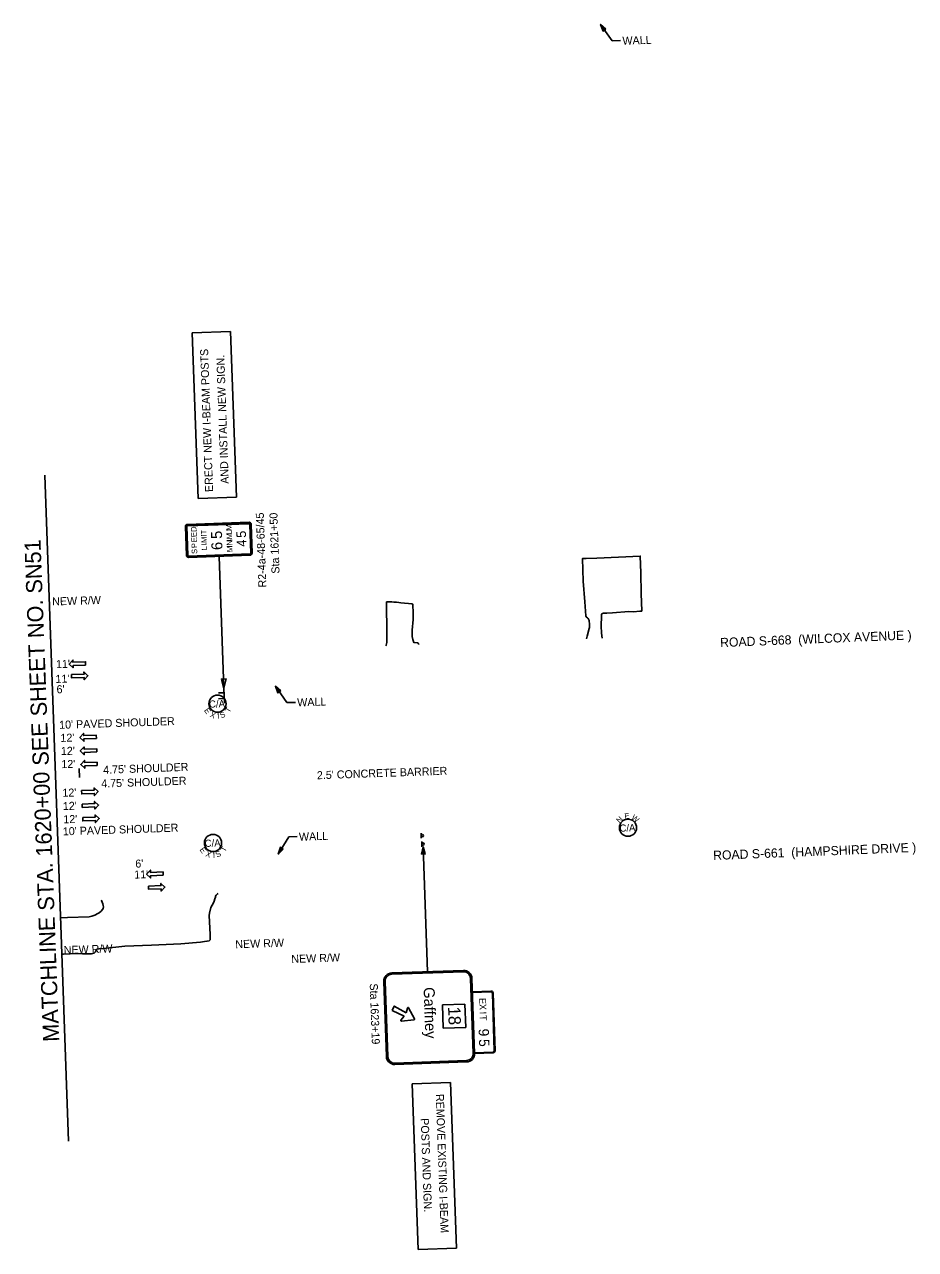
# Model space of a CAD drawing. Extents: x 1808944 to 1810496, y 1189647 to 1190718.
# Drawn here: x 1808944 to 1809723, y 1189647 to 1190718 of the extents above; entities that cross this region are included whole.
import ezdxf

# ---------------------------------------------------------------- set-up
doc = ezdxf.new("R2010")
doc.units = 0
for name, color, linetype in [('RD_EX_Road', 7, 'Continuous'), ('RD_HC_Data_Tic', 7, 'Continuous'), ('RD_PD_Final_LnLine', 7, 'Continuous'), ('RD_PD_Final_TX', 7, 'Continuous'), ('RD_PD_RW_TX', 7, 'Continuous'), ('RD_SHT_MatchLine', 7, 'Continuous'), ('RD_SHT_TX', 7, 'Continuous'), ('RD_Sketch10', 7, 'Continuous'), ('RD_Sketch8', 7, 'Continuous'), ('RD_TX_RoadID', 7, 'Continuous'), ('SN_P_Signs', 7, 'Continuous'), ('TERMINATOR', 7, 'Continuous')]:
    doc.layers.add(name, color=color, linetype=linetype)

# ---------------------------------------------------------------- blocks, each defined once
blk = doc.blocks.new('SARRW2')
at = {"layer": 'RD_PD_Final_LnLine'}
blk.add_lwpolyline([(-12, 1.2), (-12, -1.2), (-2.83, -1.2), (-2.83, -2.83), (0, 0), (-2.83, 2.83), (-2.83, 1.2)], close=True, dxfattribs=at)

msp = doc.modelspace()

# ---------------------------------------------------------------- linework, layer by layer
at = {"layer": 'RD_EX_Road'}
for points in [[(1809449, 1190181.4), (1809448.6, 1190183.4), (1809448.4, 1190186.1), (1809448.2, 1190191.8), (1809448.3, 1190200.9), (1809448.3, 1190201.5), (1809448.5, 1190202.1), (1809448.7, 1190202.6), (1809449.2, 1190202.9), (1809450.1, 1190203.1), (1809451.3, 1190203.3), (1809453.1, 1190203.3), (1809457.9, 1190203.6), (1809472.4, 1190204.6), (1809476.4, 1190204.5), (1809481.9, 1190204.9), (1809483.6, 1190205), (1809483.2, 1190220.5), (1809482.9, 1190238.4), (1809482.3, 1190253.2), (1809444.4, 1190251.3), (1809435, 1190251), (1809431.6, 1190250.9), (1809432.4, 1190231.2), (1809433.7, 1190213.1), (1809434.6, 1190200.8), (1809434.8, 1190200.1), (1809435.2, 1190199.7), (1809436, 1190199), (1809436.6, 1190198.5), (1809437, 1190198), (1809437.3, 1190197.4), (1809437.5, 1190196.7), (1809437.6, 1190195.7), (1809437.8, 1190194.5), (1809437.9, 1190193.5), (1809437.9, 1190192.4), (1809437.9, 1190191.6), (1809437.8, 1190190.8), (1809437.6, 1190189.7), (1809435.9, 1190183), (1809435.3, 1190180.9)], [(1809288.8, 1190175.7), (1809288.3, 1190176.4), (1809287.6, 1190177.3), (1809284.1, 1190177.7), (1809283.3, 1190180.2), (1809282.8, 1190182.8), (1809282.7, 1190184.2), (1809282.7, 1190188.3), (1809283.5, 1190197.6), (1809283.5, 1190204.7), (1809283.4, 1190209.3), (1809283.2, 1190211), (1809282.3, 1190211.5), (1809279.4, 1190211.7), (1809275.9, 1190212), (1809272.9, 1190212.3), (1809271.1, 1190212.5), (1809269, 1190212.7), (1809266.6, 1190212.9), (1809264.8, 1190213), (1809263, 1190213.1), (1809261.4, 1190213.1), (1809260.3, 1190213), (1809260.3, 1190207.1), (1809260.7, 1190190.9), (1809260.7, 1190180.5), (1809260.6, 1190177.5), (1809260.1, 1190175.3), (1809259.8, 1190174.7)], [(1808976.2, 1189904.9), (1808977.7, 1189905), (1808989.7, 1189905.4), (1808994.4, 1189905.3), (1808996.7, 1189905.3), (1808999.9, 1189905.2), (1809002.2, 1189905.3), (1809004.5, 1189905.7), (1809005.6, 1189907), (1809006.4, 1189908.5), (1809007, 1189909.2), (1809008.8, 1189909.6), (1809012.6, 1189910), (1809031.3, 1189911.8), (1809054.7, 1189912.8), (1809080.3, 1189914), (1809097.5, 1189915.5), (1809101, 1189915.9), (1809103.2, 1189916.2), (1809105.2, 1189916.6), (1809106.1, 1189917.5), (1809106.1, 1189919.9), (1809105.9, 1189922), (1809105.2, 1189938.6), (1809105.4, 1189940.9), (1809106.7, 1189945.8), (1809107.7, 1189947.8), (1809108.8, 1189949.7), (1809109.5, 1189951.4), (1809110.2, 1189953.3), (1809110.6, 1189954.9), (1809110.8, 1189955.7), (1809111.2, 1189956.5), (1809111.8, 1189957.1), (1809112.5, 1189957.7), (1809113, 1189957.9)], [(1809010.6, 1189952.2), (1809010.8, 1189951.8), (1809011.4, 1189950.3), (1809012, 1189948.9), (1809012.5, 1189947.6), (1809012.6, 1189946.3), (1809012.3, 1189945), (1809011.8, 1189944), (1809010.7, 1189942.6), (1809009, 1189941.2), (1809007.7, 1189940.5), (1809005, 1189938.9), (1809002.5, 1189938.1), (1809000.1, 1189937.6), (1808981.2, 1189936.9), (1808975.1, 1189936.7)]]:
    msp.add_lwpolyline(points, dxfattribs=at)
at = {"layer": 'RD_HC_Data_Tic'}
msp.add_line((1808991.6, 1190059.4), (1808991.3, 1190067.4), dxfattribs=at)
at = {"layer": 'RD_PD_Final_TX'}
for p, q in [((1809447.5, 1190718.2), (1809457.6, 1190703.8)), ((1809465.1, 1190704.1), (1809457.6, 1190703.8)), ((1809163.1, 1190139.3), (1809173.2, 1190125)), ((1809180.6, 1190125.2), (1809173.2, 1190125)), ((1809174.7, 1190007.5), (1809165.6, 1189992.5)), ((1809182.1, 1190007.8), (1809174.7, 1190007.5))]:
    msp.add_line(p, q, dxfattribs=at)
at = {"layer": 'RD_SHT_MatchLine'}
msp.add_line((1808961.4, 1190324), (1808982, 1189741.3), dxfattribs=at)
at = {"layer": 'RD_Sketch10'}
msp.add_circle((1809471.5, 1190015.5), 7.5, dxfattribs=at)
at = {"layer": 'RD_Sketch8'}
for centre in [(1809112.4, 1190124), (1809108.5, 1190002.2)]:
    msp.add_circle(centre, 7.5, dxfattribs=at)
at = {"layer": 'SN_P_Signs'}
for p, q in [((1809090.3, 1190448.5), (1809123.9, 1190449.7)), ((1809095.4, 1190303.6), (1809090.3, 1190448.5)), ((1809123.9, 1190449.7), (1809129, 1190304.8)), ((1809129, 1190304.8), (1809095.4, 1190303.6)), ((1809084.3, 1190278.9), (1809085.2, 1190253.7)), ((1809140, 1190282.7), (1809086, 1190280.7)), ((1809142.7, 1190255.7), (1809141.9, 1190280.9)), ((1809087, 1190252), (1809141, 1190253.9)), ((1809114, 1190252.9), (1809118.1, 1190137.5)), ((1809118.2, 1190133.6), (1809113.2, 1190133.4)), ((1809118.1, 1190137.5), (1809118.5, 1190124.4)), ((1809118.4, 1190128.6), (1809113.4, 1190128.4)), ((1809290.5, 1190010.8), (1809290.6, 1190006.3)), ((1809291.1, 1190003.4), (1809291.3, 1189998.9)), ((1809292.4, 1189998.7), (1809296.2, 1189889.6)), ((1809309.2, 1189860.6), (1809328.9, 1189861.3)), ((1809328.9, 1189861.3), (1809329.6, 1189840.9)), ((1809309.9, 1189840.2), (1809309.2, 1189860.6)), ((1809329.6, 1189840.9), (1809309.9, 1189840.2)), ((1809282.8, 1189791.5), (1809316.4, 1189792.7)), ((1809288, 1189646.6), (1809282.8, 1189791.5)), ((1809316.4, 1189792.7), (1809321.5, 1189647.8)), ((1809321.5, 1189647.8), (1809288, 1189646.6))]:
    msp.add_line(p, q, dxfattribs=at)
for points in [[(1809084.7, 1190278.9), (1809085.6, 1190253.7)], [(1809086.4, 1190253.7), (1809085.5, 1190278.9)], [(1809140, 1190282.2), (1809086, 1190280.3)], [(1809086.1, 1190279.5), (1809140, 1190281.5)], [(1809140.7, 1190280.9), (1809141.5, 1190255.7)], [(1809142.3, 1190255.7), (1809141.4, 1190280.9)], [(1809141, 1190255.1), (1809087, 1190253.2)], [(1809087, 1190252.4), (1809141, 1190254.3)], [(1809264.9, 1189888.5), (1809327.6, 1189890.7)], [(1809264.9, 1189887.3), (1809327.6, 1189889.5)], [(1809333.8, 1189883.7), (1809336.1, 1189818)], [(1809335, 1189883.7), (1809337.3, 1189818)], [(1809260.2, 1189815.3), (1809257.9, 1189881)], [(1809261.4, 1189815.4), (1809259.1, 1189881.1)], [(1809351.6, 1189872), (1809335.4, 1189871.4), (1809335.4, 1189872), (1809351.6, 1189872.6)], [(1809354.6, 1189820.4), (1809352.9, 1189870.8)], [(1809353.5, 1189870.8), (1809355.2, 1189820.5)], [(1809265.2, 1189855.7), (1809267.1, 1189859.5), (1809277.4, 1189853.5)], [(1809275.8, 1189850.6), (1809265.2, 1189855.7)], [(1809272.9, 1189847.3), (1809275.8, 1189850.6)], [(1809277.4, 1189853.5), (1809278.5, 1189857.8)], [(1809279.6, 1189857.9), (1809284.7, 1189848.3)], [(1809284.2, 1189847.4), (1809273.4, 1189846.3)], [(1809337.3, 1189818.6), (1809353.5, 1189819.2)], [(1809353.5, 1189818.6), (1809337.3, 1189818), (1809337.3, 1189818.6)], [(1809330.3, 1189811.8), (1809267.6, 1189809.6)], [(1809330.4, 1189810.6), (1809267.7, 1189808.4)]]:
    msp.add_lwpolyline(points, dxfattribs=at)
for points in [[(1809119.9, 1190145.7), (1809118.1, 1190137.5), (1809115.8, 1190145.6)], [(1809291, 1189992.5), (1809292.4, 1189998.7), (1809294.1, 1189992.6)]]:
    msp.add_lwpolyline(points, close=True, dxfattribs=at)
for centre in [(1809291.5, 1190008.6), (1809292.2, 1190001.2)]:
    msp.add_circle(centre, 1, dxfattribs=at)
for centre, radius, start, end in [((1809086.1, 1190279), 1.8, 92.0184, 182.0184), ((1809086.1, 1190279), 1.35, 92.0184, 182.0184), ((1809086.1, 1190279), 0.6, 92.0184, 182.0184), ((1809140.1, 1190280.9), 1.8, 2.0184, 92.0184), ((1809140.1, 1190280.9), 1.35, 2.0184, 92.0184), ((1809140.1, 1190280.9), 0.6, 2.0184, 92.0184), ((1809087, 1190253.8), 1.8, 182.0184, 272.0184), ((1809087, 1190253.8), 1.35, 182.0184, 272.0184), ((1809087, 1190253.8), 0.6, 182.0184, 272.0184), ((1809140.9, 1190255.7), 1.8, 272.0184, 2.0184), ((1809140.9, 1190255.7), 1.35, 272.0184, 2.0184), ((1809140.9, 1190255.7), 0.6, 272.0184, 2.0184), ((1809265.1, 1189881.3), 7.2, 92.0184, 182.0184), ((1809265.1, 1189881.3), 6, 92.0184, 182.0184), ((1809327.8, 1189883.5), 7.2, 2.0184, 92.0184), ((1809327.8, 1189883.5), 6, 2.0184, 92.0184), ((1809351.7, 1189870.8), 1.8, 2.0184, 92.0184), ((1809351.7, 1189870.8), 1.2, 2.0184, 92.0184), ((1809279.1, 1189857.6), 0.6, 27.9991, 165.4645), ((1809273.4, 1189846.9), 0.6, 138.5723, 276.0378), ((1809284.2, 1189848), 0.6, 276.0378, 27.9991), ((1809353.4, 1189820.4), 1.8, 272.0184, 2.0184), ((1809353.4, 1189820.4), 1.2, 272.0184, 2.0184), ((1809267.4, 1189815.6), 7.2, 182.0184, 272.0184), ((1809267.4, 1189815.6), 6, 182.0184, 272.0184), ((1809330.1, 1189817.8), 6, 272.0184, 2.0184), ((1809330.1, 1189817.8), 7.2, 272.0184, 2.0184)]:
    msp.add_arc(centre, radius, start, end, dxfattribs=at)
at = {"layer": 'TERMINATOR'}
for points in [[(1809452.2, 1190714.1), (1809447.5, 1190718.2), (1809449.7, 1190712.4)], [(1809167.7, 1190135.3), (1809163.1, 1190139.3), (1809165.3, 1190133.5)], [(1809169.9, 1189996.9), (1809165.6, 1189992.5), (1809167.4, 1189998.4)]]:
    msp.add_lwpolyline(points, close=True, dxfattribs=at)

# ---------------------------------------------------------------- block references
at = {"layer": 'RD_PD_Final_LnLine', "xscale": 1.1999999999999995, "yscale": 1.2000000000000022}
for p, rotation in [((1808982.6, 1190158.7), -177.9816202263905), ((1808999.1, 1190148.5), 2.018379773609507), ((1808992, 1190094.5), -177.9816202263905), ((1808992.4, 1190082.7), -177.9816202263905), ((1808992.8, 1190070.9), -177.9816202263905), ((1809008, 1190047.1), 2.018379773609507), ((1809008.4, 1190035.3), 2.018379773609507), ((1809008.9, 1190023.5), 2.018379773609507), ((1809050.4, 1189974.9), -177.9816202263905), ((1809066.4, 1189963.6), 2.018379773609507)]:
    msp.add_blockref('SARRW2', p, dxfattribs=dict(at, rotation=rotation))

# ---------------------------------------------------------------- texts
at = {"layer": 'RD_PD_Final_TX'}
for s, rotation, p in [('WALL', 2.0184, (1809466.8, 1190700.4)), ("11'", 1.7095, (1808971.2, 1190155.1)), ("11'", 1.5309, (1808970.8, 1190142.2)), ("6'", 1.3916, (1808971.7, 1190133.1)), ('WALL', 2.0184, (1809182.3, 1190121.6)), ("10' PAVED SHOULDER", 1.9045, (1808974, 1190102)), ("12'", 1.3916, (1808975.1, 1190090.6)), ("12'", 1.3916, (1808975.5, 1190079.1)), ("12'", 1.3916, (1808975.9, 1190067.6)), ("4.75' SHOULDER", 2.0184, (1809012.5, 1190062.7)), ("2.5' CONCRETE BARRIER", 2.0201, (1809199.5, 1190057.9)), ("4.75' SHOULDER", 2.0184, (1809010.8, 1190050.6)), ("12'", 1.3916, (1808976.8, 1190042.6)), ("12'", 1.3916, (1808977.2, 1190031)), ("12'", 1.3916, (1808977.6, 1190019.4)), ("10' PAVED SHOULDER", 1.9045, (1808977.2, 1190008.8)), ('WALL', 2.0184, (1809183.8, 1190004.1)), ("6'", 1.3916, (1809040.6, 1189980.6)), ("11'", 2.0184, (1809039.7, 1189971))]:
    msp.add_text(s, height=7, rotation=rotation, dxfattribs=at).set_placement(p)
at = {"layer": 'RD_PD_RW_TX'}
for p in [(1808967.9, 1190209.9), (1809128.1, 1189910.1), (1808978, 1189905), (1809177.1, 1189897.2)]:
    msp.add_text('NEW R/W', height=7, rotation=1.8866, dxfattribs=at).set_placement(p)
at = {"layer": 'RD_SHT_TX'}
msp.add_text('MATCHLINE STA. 1620+00 SEE SHEET NO. SN51', height=14.173, rotation=92.1424, dxfattribs=at).set_placement((1808974, 1189828.5))
at = {"layer": 'RD_Sketch10'}
for s, height, rotation, p in [('N', 5, 46.8882, (1809464.3, 1190019.1)), ('E', 5, 6.3514, (1809468.7, 1190023.1)), ('W', 5, 321.321, (1809473.9, 1190023.5)), ('C/A', 6.25, 2.0184, (1809464.2, 1190012))]:
    msp.add_text(s, height=height, rotation=rotation, dxfattribs=at).set_placement(p)
at = {"layer": 'RD_Sketch8'}
for s, height, rotation, p in [('E', 5, 305.2296, (1809100.4, 1190118.1)), ('C/A', 6.25, 2.0184, (1809105.1, 1190120.5)), ('T', 5, 60.2035, (1809122.9, 1190115.7)), ('X', 5, 337.659, (1809105.3, 1190112.6)), ('I', 5, 1.819, (1809112.2, 1190110.8)), ('S', 5, 23.8108, (1809115.8, 1190111.1)), ('C/A', 6.25, 2.0184, (1809101.3, 1189998.7)), ('E', 5, 305.2296, (1809096.5, 1189996.3)), ('X', 5, 337.659, (1809101.5, 1189990.8)), ('I', 5, 1.819, (1809108.4, 1189989)), ('S', 5, 23.8108, (1809112, 1189989.3)), ('T', 5, 60.2035, (1809119, 1189993.9))]:
    msp.add_text(s, height=height, rotation=rotation, dxfattribs=at).set_placement(p)
at = {"layer": 'RD_TX_RoadID'}
for s, p in [('ROAD S-668  (WILCOX AVENUE )', (1809552.3, 1190173.5)), ('ROAD S-661  (HAMPSHIRE DRIVE )', (1809546.2, 1189987.3))]:
    msp.add_text(s, height=8, rotation=2.2938, dxfattribs=at).set_placement(p)
at = {"layer": 'SN_P_Signs'}
for s, height, rotation, p in [('ERECT NEW I-BEAM POSTS', 7, 92.0185, (1809108.6, 1190309.3)), ('AND INSTALL NEW SIGN.', 7, 92.0185, (1809122.3, 1190316.5)), ('R2-4a-48-65/45', 7, 92.0185, (1809155.2, 1190225.8)), ('Sta 1621+50', 7, 92.0185, (1809166.7, 1190237.9)), ('M', 4.8, 92.0184, (1809124.9, 1190275.6)), ('D', 4.8, 92.0184, (1809094.1, 1190274.4)), ('E', 4.8, 92.0184, (1809094.2, 1190269.8)), ('E', 4.8, 92.0184, (1809094.4, 1190265.3)), ('T', 4.8, 92.0184, (1809102.8, 1190272.2)), ('I', 4.8, 92.0184, (1809102.9, 1190270.4)), ('M', 4.8, 92.0184, (1809103.1, 1190264.7)), ('5', 9.6, 92.0184, (1809116.5, 1190268.3)), ('U', 4.8, 92.0184, (1809125.1, 1190272)), ('M', 4.8, 92.0184, (1809125.2, 1190267.9)), ('5', 8.4, 92.0184, (1809137.5, 1190269.2)), ('P', 4.8, 92.0184, (1809094.6, 1190260.2)), ('S', 4.8, 92.0184, (1809094.7, 1190255.1)), ('I', 4.8, 92.0184, (1809103.2, 1190262.7)), ('L', 4.8, 92.0184, (1809103.3, 1190258.2)), ('6', 9.6, 92.0184, (1809116.8, 1190258.6)), ('I', 4.8, 92.0184, (1809125.3, 1190266.2)), ('N', 4.8, 92.0184, (1809125.4, 1190262.5)), ('I', 4.8, 92.0184, (1809125.4, 1190260.8)), ('M', 4.8, 92.0184, (1809125.6, 1190256.7)), ('4', 8.4, 92.0184, (1809137.7, 1190261.5)), ('Sta 1623+19', 7, 272.0185, (1809245.6, 1189879.2)), ('Gaffney', 9.6, 272.0184, (1809292.7, 1189875.9)), ('E', 6, 272.0184, (1809341.3, 1189866.5)), ('X', 6, 272.0184, (1809341.5, 1189861.3)), ('18', 10.8, 272.0184, (1809314.1, 1189858.8)), ('I', 6, 272.0184, (1809341.7, 1189854.5)), ('T', 6, 272.0184, (1809341.8, 1189851.5)), ('9', 9, 272.0184, (1809340.8, 1189839.6)), ('5', 9, 272.0184, (1809341.1, 1189830.5)), ('REMOVE EXISTING I-BEAM', 7, 272.0185, (1809303.4, 1189782.5)), ('POSTS AND SIGN. ', 7, 272.0185, (1809290.2, 1189761.3))]:
    msp.add_text(s, height=height, rotation=rotation, dxfattribs=at).set_placement(p)

doc.saveas('drawing.dxf')
